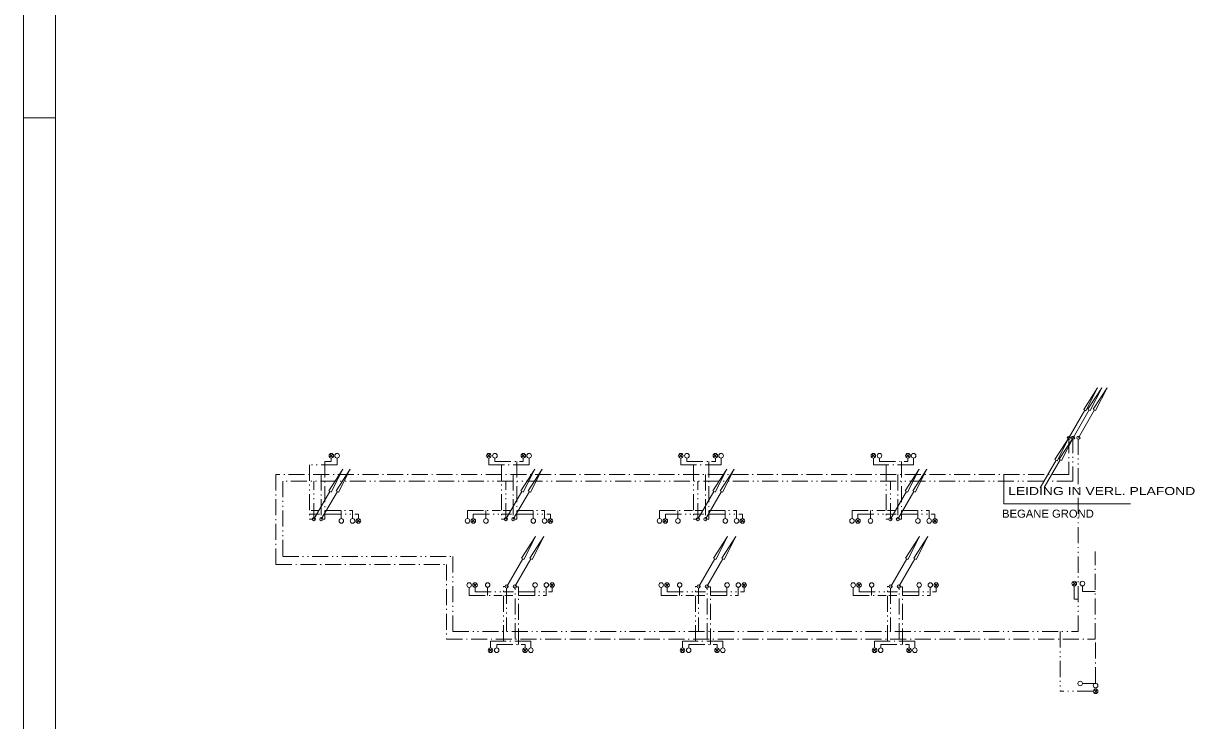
# Model space of a CAD drawing. Extents: x 295824 to 414724, y 24924 to 109024.
# Drawn here: x 295824 to 332398, y 65507 to 87265 of the extents above; entities that cross this region are included whole.
import ezdxf

# ---------------------------------------------------------------- set-up
doc = ezdxf.new("R2010")
doc.units = 0
doc.header["$LTSCALE"] = 100
doc.linetypes.add('DASH_DOUBLE_DOT', pattern=[9.2, 5, -1.2, 0.3, -1.2, 0.3, -1.2])
doc.linetypes.add('DOT_DASHED', pattern=[7.7, 5, -1.2, 0.3, -1.2])
for name, color, linetype, lineweight in [('1', 7, 'Continuous', 13), ('16', 7, 'Continuous', 13), ('30', 7, 'Continuous', 13)]:
    doc.layers.add(name, color=color, linetype=linetype, lineweight=lineweight)

msp = doc.modelspace()

# ---------------------------------------------------------------- linework, layer by layer
at = {"layer": '1'}
for p, q in [((295823.6, 109023.8), (295823.6, 24923.8)), ((295823.6, 84323.8), (296823.6, 84323.8))]:
    msp.add_line(p, q, dxfattribs=at)
msp.add_lwpolyline([(304995.6, 108023.8), (296823.6, 108023.8), (296823.6, 25923.8), (304995.6, 25923.8)], dxfattribs=at)
at = {"layer": '30'}
for p, q in [((328470.9, 74327.9), (328970.9, 75193.9)), ((328604.2, 74336.2), (329104.2, 75202.2)), ((328770.7, 74336.2), (329270.7, 75202.2)), ((305486.5, 73826.1), (305385.3, 73724.9)), ((305389.3, 73824), (305490.7, 73722.7)), ((310404.4, 73826.1), (310303.2, 73724.9)), ((310307.2, 73824), (310408.6, 73722.7)), ((311482.9, 73826.1), (311381.7, 73724.9)), ((311385.7, 73824), (311487, 73722.7)), ((316400.7, 73826.1), (316299.6, 73724.9)), ((316303.6, 73824), (316404.9, 73722.7)), ((317479.2, 73826.1), (317378.1, 73724.9)), ((317382.1, 73824), (317483.4, 73722.7)), ((322413.7, 73826.1), (322312.6, 73724.9)), ((322316.6, 73824), (322417.9, 73722.7)), ((323492.2, 73826.1), (323391.1, 73724.9)), ((323395.1, 73824), (323496.4, 73722.7)), ((327570.9, 72768.9), (328070.9, 73634.9)), ((327704.2, 72777.2), (328204.2, 73643.2)), ((326442.7, 73172), (326442.7, 72272)), ((304893.6, 71793.2), (305393.6, 72659.2)), ((305126.8, 71793.2), (305626.8, 72659.2)), ((310889.9, 71793.2), (311389.9, 72659.2)), ((311123.1, 71793.2), (311623.1, 72659.2)), ((316886.3, 71793.2), (317386.3, 72659.2)), ((317119.5, 71793.2), (317619.5, 72659.2)), ((322899.3, 71793.2), (323399.3, 72659.2)), ((323132.5, 71793.2), (323632.5, 72659.2)), ((326442.7, 72272), (330401.9, 72272)), ((306332.8, 71790.8), (306231.6, 71689.7)), ((306235.7, 71788.7), (306337, 71687.4)), ((309921.3, 71792.8), (309820.2, 71691.6)), ((309824.2, 71790.7), (309925.5, 71689.4)), ((312329.2, 71790.8), (312228, 71689.7)), ((312232, 71788.7), (312333.4, 71687.4)), ((315917.7, 71792.8), (315816.5, 71691.6)), ((315820.5, 71790.7), (315921.9, 71689.4)), ((318325.5, 71790.8), (318224.4, 71689.7)), ((318228.4, 71788.7), (318329.7, 71687.4)), ((321930.7, 71792.8), (321829.5, 71691.6)), ((321833.6, 71790.7), (321934.9, 71689.4)), ((324338.5, 71790.8), (324237.4, 71689.7)), ((324241.4, 71788.7), (324342.7, 71687.4)), ((310915, 69693.3), (311415, 70559.3)), ((311171.2, 69693.3), (311671.2, 70559.3)), ((316911.4, 69693.3), (317411.4, 70559.3)), ((317167.5, 69693.3), (317667.5, 70559.3)), ((322907.7, 69693.3), (323407.7, 70559.3)), ((323163.8, 69693.3), (323663.8, 70559.3)), ((309975.6, 69681.4), (309874.4, 69782.5)), ((309878.4, 69683.4), (309979.8, 69784.8)), ((312383.4, 69683.3), (312282.3, 69784.5)), ((312286.3, 69685.4), (312387.6, 69786.7)), ((315971.9, 69681.4), (315870.7, 69782.5)), ((315874.7, 69683.4), (315976.1, 69784.8)), ((318379.7, 69683.3), (318278.6, 69784.5)), ((318282.6, 69685.4), (318383.9, 69786.7)), ((321968.2, 69681.4), (321867, 69782.5)), ((321871, 69683.4), (321972.4, 69784.8)), ((324376, 69683.3), (324274.9, 69784.5)), ((324278.9, 69685.4), (324380.2, 69786.7)), ((328692.2, 69732.3), (328590.8, 69833.7)), ((328694.2, 69829.5), (328593.1, 69728.3)), ((310458.6, 67648.1), (310357.5, 67749.2)), ((310361.5, 67650.1), (310462.8, 67751.5)), ((311537.1, 67648.1), (311436, 67749.2)), ((311440, 67650.1), (311541.3, 67751.5)), ((316454.9, 67648.1), (316353.8, 67749.2)), ((316357.8, 67650.1), (316459.1, 67751.5)), ((317533.4, 67648.1), (317432.3, 67749.2)), ((317436.3, 67650.1), (317537.6, 67751.5)), ((322451.2, 67648.1), (322350.1, 67749.2)), ((322354.1, 67650.1), (322455.4, 67751.5)), ((323529.7, 67648.1), (323428.6, 67749.2)), ((323432.6, 67650.1), (323533.9, 67751.5)), ((329358.4, 66369.9), (329257.1, 66471.2)), ((329360.5, 66467), (329259.4, 66365.9))]:
    msp.add_line(p, q, dxfattribs=at)
at = {"layer": '30', "linetype": 'DASH_DOUBLE_DOT'}
for p, q in [((328598.6, 74357.8), (328598.6, 72982.9)), ((328765.2, 68283), (328765.2, 74306.1)), ((305618.1, 73700.7), (305618.1, 73491.3)), ((310356.9, 73700.7), (310356.9, 73491.3)), ((311614.5, 73700.7), (311614.5, 73491.3)), ((316353.3, 73700.7), (316353.3, 73491.3)), ((317610.8, 73700.7), (317610.8, 73491.3)), ((322366.3, 73700.7), (322366.3, 73491.3)), ((323623.9, 73700.7), (323623.9, 73491.3)), ((305618.1, 73491.3), (304760.3, 73491.3)), ((304760.3, 73491.3), (304760.3, 71788.7)), ((310723.4, 73491.3), (310356.9, 73491.3)), ((310723.4, 73491.3), (310810.8, 73491.3)), ((310756.7, 73491.3), (310756.7, 71788.7)), ((311614.5, 73491.3), (310810.8, 73491.3)), ((316719.7, 73491.3), (316353.3, 73491.3)), ((316719.7, 73491.3), (316807.2, 73491.3)), ((316753, 73491.3), (316753, 71788.7)), ((317610.8, 73491.3), (316807.2, 73491.3)), ((322732.7, 73491.3), (322366.3, 73491.3)), ((322732.7, 73491.3), (322820.2, 73491.3)), ((322766, 73491.3), (322766, 71788.7)), ((323623.9, 73491.3), (322820.2, 73491.3)), ((328598.6, 72982.9), (303922.4, 72982.9)), ((304893.6, 71793.2), (304893.6, 72982.9)), ((310889.9, 71793.2), (310889.9, 72982.9)), ((316886.3, 71793.2), (316886.3, 72982.9)), ((322899.3, 71793.2), (322899.3, 72982.9)), ((304760.3, 71944.5), (305073.4, 71944.5)), ((304843.6, 71788.7), (304760.3, 71788.7)), ((305248.3, 71944.5), (306285.4, 71944.5)), ((306285.4, 71808.8), (306285.4, 71944.5)), ((309873.9, 71810.7), (309873.9, 71944.5)), ((310839.9, 71788.7), (310756.7, 71788.7)), ((311244.7, 71944.5), (312281.7, 71944.5)), ((312281.7, 71808.8), (312281.7, 71944.5)), ((315870.2, 71810.7), (315870.2, 71944.5)), ((316836.3, 71788.7), (316753, 71788.7)), ((317241, 71944.5), (318278.1, 71944.5)), ((318278.1, 71808.8), (318278.1, 71944.5)), ((321883.3, 71810.7), (321883.3, 71944.5)), ((322849.3, 71788.7), (322766, 71788.7)), ((323254, 71944.5), (324291.1, 71944.5)), ((324291.1, 71808.8), (324291.1, 71944.5)), ((309928.1, 69663.4), (309928.1, 69529.6)), ((310866.9, 69693.8), (310810.9, 69693.8)), ((310810.9, 67982.8), (310810.9, 69693.8)), ((310910.9, 69647.6), (310910.9, 68283)), ((311298.9, 69529.6), (312336, 69529.6)), ((312336, 69665.4), (312336, 69529.6)), ((315924.4, 69663.4), (315924.4, 69529.6)), ((316863.2, 69693.8), (316807.2, 69693.8)), ((316807.2, 67982.8), (316807.2, 69693.8)), ((316907.2, 69647.6), (316907.2, 68283)), ((317295.2, 69529.6), (318332.3, 69529.6)), ((318332.3, 69665.4), (318332.3, 69529.6)), ((321920.7, 69663.4), (321920.7, 69529.6)), ((322859.5, 69693.8), (322803.5, 69693.8)), ((322803.5, 67982.8), (322803.5, 69693.8)), ((322903.5, 69647.6), (322903.5, 68283)), ((323291.5, 69529.6), (324328.6, 69529.6)), ((324328.6, 69665.4), (324328.6, 69529.6)), ((328640.5, 69710.4), (328640.5, 69294.6)), ((328640.5, 69294.6), (328765.2, 69294.6)), ((328196.1, 68286.3), (328196.1, 66419.6)), ((310411.2, 67773.4), (310411.2, 67982.8)), ((310777.6, 67982.8), (310411.2, 67982.8)), ((310777.6, 67982.8), (310865, 67982.8)), ((311668.7, 67982.8), (310865, 67982.8)), ((311668.7, 67773.4), (311668.7, 67982.8)), ((316407.5, 67773.4), (316407.5, 67982.8)), ((316773.9, 67982.8), (316407.5, 67982.8)), ((316773.9, 67982.8), (316861.4, 67982.8)), ((317665, 67982.8), (316861.4, 67982.8)), ((317665, 67773.4), (317665, 67982.8)), ((322403.8, 67773.4), (322403.8, 67982.8)), ((322770.2, 67982.8), (322403.8, 67982.8)), ((322770.2, 67982.8), (322857.7, 67982.8)), ((323661.3, 67982.8), (322857.7, 67982.8)), ((323661.3, 67773.4), (323661.3, 67982.8)), ((329235.1, 66419.6), (328196.1, 66419.6))]:
    msp.add_line(p, q, dxfattribs=at)
at = {"layer": '30', "linetype": 'DOT_DASHED'}
for p, q in [((305235, 73589.2), (305439.1, 73589.2)), ((305235, 73589.2), (305235, 71797)), ((305439.1, 73700.7), (305439.1, 73589.2)), ((311231.4, 73592.8), (311231.4, 71797)), ((311435.4, 73700.7), (311435.4, 73589.2)), ((317227.7, 73592.8), (317227.7, 71797)), ((317431.8, 73700.7), (317431.8, 73589.2)), ((323240.8, 73592.8), (323240.8, 71797)), ((323444.8, 73700.7), (323444.8, 73589.2)), ((305126.8, 73182.9), (305126.8, 71818.2)), ((311123.1, 73182.9), (311123.1, 71818.2)), ((317119.5, 73182.9), (317119.5, 71818.2)), ((323132.5, 73182.9), (323132.5, 71818.2)), ((304806.1, 72065.3), (305060.1, 72065.3)), ((305235, 72065.3), (306102.2, 72065.3)), ((305748.2, 71808.8), (305748.2, 72065.3)), ((306102.2, 71808.8), (306102.2, 72065.3)), ((309690.7, 71810.8), (309690.7, 72065.3)), ((309690.7, 72065.3), (310723.4, 72065.3)), ((310266.3, 71808.8), (310266.3, 72065.3)), ((310802.5, 72065.3), (311056.5, 72065.3)), ((311231.4, 72065.3), (312098.5, 72065.3)), ((311744.6, 71808.8), (311744.6, 72065.3)), ((312098.5, 71808.8), (312098.5, 72065.3)), ((315687, 71810.8), (315687, 72065.3)), ((315687, 72065.3), (316719.7, 72065.3)), ((316262.7, 71808.8), (316262.7, 72065.3)), ((316798.8, 72065.3), (317052.8, 72065.3)), ((317227.7, 72065.3), (318094.9, 72065.3)), ((317740.9, 71808.8), (317740.9, 72065.3)), ((318094.9, 71808.8), (318094.9, 72065.3)), ((321700.1, 71810.8), (321700.1, 72065.3)), ((321700.1, 72065.3), (322732.7, 72065.3)), ((322275.7, 71808.8), (322275.7, 72065.3)), ((322811.9, 72065.3), (323065.9, 72065.3)), ((323240.8, 72065.3), (324107.9, 72065.3)), ((323754, 71808.8), (323754, 72065.3)), ((324107.9, 71808.8), (324107.9, 72065.3)), ((305172.5, 71797), (305235, 71797)), ((311168.9, 71797), (311231.4, 71797)), ((317165.3, 71797), (317227.7, 71797)), ((323178.3, 71797), (323240.8, 71797)), ((329298.2, 68049.6), (329298.2, 70782.9)), ((309744.9, 69663.4), (309744.9, 69408.8)), ((310320.6, 69665.3), (310320.6, 69408.8)), ((311177.4, 68049.6), (311177.4, 69655.9)), ((311223.2, 69677.1), (311285.6, 69677.1)), ((311285.6, 67881.3), (311285.6, 69677.1)), ((311798.8, 69665.3), (311798.8, 69408.8)), ((312152.8, 69665.3), (312152.8, 69408.8)), ((315741.2, 69663.4), (315741.2, 69408.8)), ((316316.9, 69665.3), (316316.9, 69408.8)), ((317173.7, 68049.6), (317173.7, 69655.9)), ((317219.5, 69677.1), (317281.9, 69677.1)), ((317281.9, 67881.3), (317281.9, 69677.1)), ((317795.1, 69665.3), (317795.1, 69408.8)), ((318149.1, 69665.3), (318149.1, 69408.8)), ((321737.5, 69663.4), (321737.5, 69408.8)), ((322313.2, 69665.3), (322313.2, 69408.8)), ((323170, 68049.6), (323170, 69655.9)), ((323215.8, 69677.1), (323278.2, 69677.1)), ((323278.2, 67881.3), (323278.2, 69677.1)), ((323791.4, 69665.3), (323791.4, 69408.8)), ((324145.4, 69665.3), (324145.4, 69408.8)), ((309744.9, 69408.8), (310777.6, 69408.8)), ((310856.7, 69408.8), (311110.7, 69408.8)), ((311285.6, 69408.8), (312152.8, 69408.8)), ((315741.2, 69408.8), (316773.9, 69408.8)), ((316853, 69408.8), (317107, 69408.8)), ((317281.9, 69408.8), (318149.1, 69408.8)), ((321737.5, 69408.8), (322770.2, 69408.8)), ((322849.3, 69408.8), (323103.3, 69408.8)), ((323278.2, 69408.8), (324145.4, 69408.8)), ((329306.8, 66670.3), (329306.8, 68049.6)), ((311489.7, 67773.4), (311489.7, 67884.9)), ((317486, 67773.4), (317486, 67884.9)), ((323482.3, 67773.4), (323482.3, 67884.9)), ((328895.7, 66661.3), (329312.1, 66661.3))]:
    msp.add_line(p, q, dxfattribs=at)
at = {"layer": '30'}
for points in [[(329370.9, 75886.9), (329006.9, 75172.9), (328934.9, 75214.9)], [(329504.2, 75895.2), (329140.2, 75181.2), (329068.2, 75223.2)], [(329670.7, 75895.2), (329306.7, 75181.2), (329234.7, 75223.2)], [(328470.9, 74327.9), (328106.9, 73613.9), (328034.9, 73655.9)], [(328604.2, 74336.2), (328240.2, 73622.2), (328168.2, 73664.2)], [(305793.6, 73352.2), (305429.6, 72638.2), (305357.6, 72680.2)], [(306026.8, 73352.2), (305662.8, 72638.2), (305590.8, 72680.2)], [(311789.9, 73352.2), (311425.9, 72638.2), (311353.9, 72680.2)], [(312023.1, 73352.2), (311659.1, 72638.2), (311587.1, 72680.2)], [(317786.3, 73352.2), (317422.3, 72638.2), (317350.3, 72680.2)], [(318019.5, 73352.2), (317655.5, 72638.2), (317583.5, 72680.2)], [(323799.3, 73352.2), (323435.3, 72638.2), (323363.3, 72680.2)], [(324032.5, 73352.2), (323668.5, 72638.2), (323596.5, 72680.2)], [(311815, 71252.3), (311451, 70538.3), (311379, 70580.3)], [(312071.2, 71252.3), (311707.2, 70538.3), (311635.2, 70580.3)], [(317811.4, 71252.3), (317447.4, 70538.3), (317375.4, 70580.3)], [(318067.5, 71252.3), (317703.5, 70538.3), (317631.5, 70580.3)], [(323807.7, 71252.3), (323443.7, 70538.3), (323371.7, 70580.3)], [(324063.8, 71252.3), (323699.8, 70538.3), (323627.8, 70580.3)]]:
    msp.add_lwpolyline(points, close=True, dxfattribs=at)
at = {"layer": '30', "linetype": 'DOT_DASHED'}
for points in [[(328473.7, 74349.5), (328473.7, 73182.9), (303705.8, 73182.9), (303705.8, 70382.9), (309035.8, 70382.9), (309035.8, 68049.6), (329298.2, 68049.6)], [(310548.5, 73700.7), (310548.5, 73589.2), (311435.4, 73589.2)], [(316544.8, 73700.7), (316544.8, 73589.2), (317431.8, 73589.2)], [(322557.9, 73700.7), (322557.9, 73589.2), (323444.8, 73589.2)], [(328894.5, 69710.2), (328894.5, 69536.3), (329298.2, 69536.3)], [(310602.7, 67773.4), (310602.7, 67884.9), (311489.7, 67884.9)], [(316599, 67773.4), (316599, 67884.9), (317486, 67884.9)], [(322595.3, 67773.4), (322595.3, 67884.9), (323482.3, 67884.9)]]:
    msp.add_lwpolyline(points, dxfattribs=at)
at = {"layer": '30', "linetype": 'DASH_DOUBLE_DOT'}
for points in [[(303922.4, 72982.9), (303922.4, 70624.6), (309235.7, 70624.6), (309235.7, 68283), (328765.2, 68283)], [(309873.9, 71944.5), (310756.7, 71944.5), (311069.8, 71944.5)], [(315870.2, 71944.5), (316753, 71944.5), (317066.1, 71944.5)], [(321883.3, 71944.5), (322766, 71944.5), (323079.2, 71944.5)], [(309928.1, 69529.6), (310810.9, 69529.6), (311124, 69529.6)], [(315924.4, 69529.6), (316807.2, 69529.6), (317120.3, 69529.6)], [(321920.7, 69529.6), (322803.5, 69529.6), (323116.6, 69529.6)]]:
    msp.add_lwpolyline(points, dxfattribs=at)
at = {"layer": '30'}
for centre, radius in [((328470.9, 74327.6), 50), ((328470.9, 74327.6), 50), ((328604.2, 74335.9), 50), ((328604.2, 74335.9), 50), ((328770.7, 74335.9), 50), ((305439.1, 73772.4), 71.7), ((305618.1, 73772.4), 71.7), ((310356.9, 73772.4), 71.7), ((310548.5, 73772.4), 71.7), ((311435.4, 73772.4), 71.7), ((311614.5, 73772.4), 71.7), ((316353.3, 73772.4), 71.7), ((316544.8, 73772.4), 71.7), ((317431.8, 73772.4), 71.7), ((317610.8, 73772.4), 71.7), ((322366.3, 73772.4), 71.7), ((322557.9, 73772.4), 71.7), ((323444.8, 73772.4), 71.7), ((323623.9, 73772.4), 71.7), ((304893.6, 71792.9), 50), ((305126.8, 71792.9), 50), ((305752.4, 71737.1), 71.7), ((306102.2, 71737.1), 71.7), ((306285.4, 71737.1), 71.7), ((309690.7, 71739.1), 71.7), ((309873.9, 71739.1), 71.7), ((310266.3, 71737.1), 71.7), ((310889.9, 71792.9), 50), ((311123.1, 71792.9), 50), ((311748.7, 71737.1), 71.7), ((312098.5, 71737.1), 71.7), ((312281.7, 71737.1), 71.7), ((315687, 71739.1), 71.7), ((315870.3, 71739.1), 71.7), ((316262.7, 71737.1), 71.7), ((316886.3, 71792.9), 50), ((317119.5, 71792.9), 50), ((317745.1, 71737.1), 71.7), ((318094.9, 71737.1), 71.7), ((318278.1, 71737.1), 71.7), ((321700.1, 71739.1), 71.7), ((321883.3, 71739.1), 71.7), ((322275.7, 71737.1), 71.7), ((322899.3, 71792.9), 50), ((323132.5, 71792.9), 50), ((323758.1, 71737.1), 71.7), ((324107.9, 71737.1), 71.7), ((324291.1, 71737.1), 71.7), ((309744.9, 69735.1), 71.7), ((309928.2, 69735.1), 71.7), ((310320.6, 69737), 71.7), ((310915, 69693), 50), ((311171.1, 69693), 50), ((311803, 69737), 71.7), ((312152.8, 69737), 71.7), ((312336, 69737), 71.7), ((315741.2, 69735.1), 71.7), ((315924.5, 69735.1), 71.7), ((316316.9, 69737), 71.7), ((316911.3, 69693), 50), ((317167.4, 69693), 50), ((317799.3, 69737), 71.7), ((318149.1, 69737), 71.7), ((318332.3, 69737), 71.7), ((321737.5, 69735.1), 71.7), ((321920.8, 69735.1), 71.7), ((322313.2, 69737), 71.7), ((322907.6, 69693), 50), ((323163.7, 69693), 50), ((323795.6, 69737), 71.7), ((324145.4, 69737), 71.7), ((324328.6, 69737), 71.7), ((328640.5, 69782), 71.7), ((328894.5, 69781.9), 71.7), ((310411.2, 67701.8), 71.7), ((310602.7, 67701.8), 71.7), ((311489.7, 67701.8), 71.7), ((311668.7, 67701.8), 71.7), ((316407.5, 67701.8), 71.7), ((316599, 67701.8), 71.7), ((317486, 67701.8), 71.7), ((317665, 67701.8), 71.7), ((322403.8, 67701.8), 71.7), ((322595.3, 67701.8), 71.7), ((323482.3, 67701.8), 71.7), ((323661.3, 67701.8), 71.7), ((328823.8, 66665.3), 71.7), ((329306.8, 66598.6), 71.7), ((329306.8, 66419.6), 71.7)]:
    msp.add_circle(centre, radius, dxfattribs=at)

# ---------------------------------------------------------------- texts
at = {"layer": '16'}
for s, width, p in [('LEIDING IN VERL. PLAFOND', 1.3, (326574.3, 72545.7)), ('BEGANE GROND', 1.05, (326385.1, 71839.6))]:
    msp.add_text(s, height=250, dxfattribs=dict(at, width=width)).set_placement(p)

doc.saveas('drawing.dxf')
